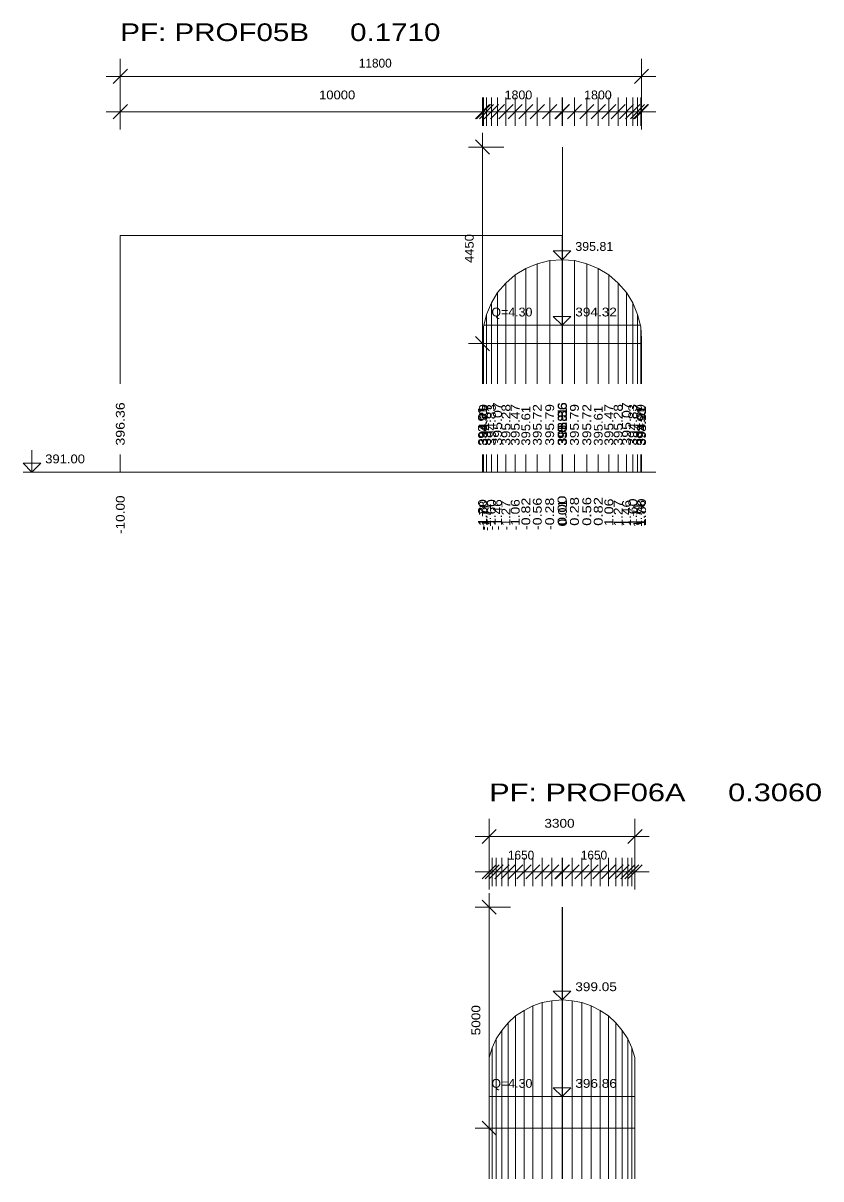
# Model space of a CAD drawing. Extents: x 7 to 442, y -393 to 441.
# Drawn here: x 409.84 to 427.9, y 82.97 to 109.13 of the extents above; entities that cross this region are included whole.
import ezdxf

# ---------------------------------------------------------------- set-up
doc = ezdxf.new("R2010")
doc.units = 0
doc.header["$LTSCALE"] = 0.08
doc.layers.add('7', color=7, linetype='Continuous', lineweight=13)

msp = doc.modelspace()

# ---------------------------------------------------------------- linework, layer by layer
at = {"layer": '7'}
for p, q in [((411.878, 107.766), (412.198, 108.086)), ((412.038, 106.726), (412.038, 108.326)), ((423.678, 107.766), (423.998, 108.086)), ((423.838, 106.726), (423.838, 108.326)), ((411.718, 107.926), (424.158, 107.926)), ((411.878, 106.966), (412.198, 107.286)), ((412.038, 106.806), (412.038, 107.446)), ((420.078, 106.966), (420.398, 107.286)), ((420.078, 106.966), (420.398, 107.286)), ((420.098, 106.966), (420.418, 107.286)), ((420.168, 106.966), (420.488, 107.286)), ((420.238, 106.806), (420.238, 107.446)), ((420.238, 106.806), (420.238, 107.446)), ((420.258, 106.806), (420.258, 107.446)), ((420.278, 106.966), (420.598, 107.286)), ((420.328, 106.806), (420.328, 107.446)), ((420.418, 106.966), (420.738, 107.286)), ((420.438, 106.806), (420.438, 107.446)), ((420.578, 106.806), (420.578, 107.446)), ((420.608, 106.966), (420.928, 107.286)), ((420.768, 106.806), (420.768, 107.446)), ((420.818, 106.966), (421.138, 107.286)), ((420.978, 106.806), (420.978, 107.446)), ((421.058, 106.966), (421.378, 107.286)), ((421.218, 106.806), (421.218, 107.446)), ((421.318, 106.966), (421.638, 107.286)), ((421.478, 106.806), (421.478, 107.446)), ((421.598, 106.966), (421.918, 107.286)), ((421.758, 106.806), (421.758, 107.446)), ((421.878, 106.966), (422.198, 107.286)), ((421.878, 106.966), (422.198, 107.286)), ((421.878, 106.966), (422.198, 107.286)), ((421.888, 106.966), (422.208, 107.286)), ((421.888, 106.966), (422.208, 107.286)), ((422.038, 106.806), (422.038, 107.446)), ((422.038, 106.806), (422.038, 107.446)), ((422.038, 106.806), (422.038, 107.446)), ((422.048, 106.806), (422.048, 107.446)), ((422.048, 106.806), (422.048, 107.446)), ((422.158, 106.966), (422.478, 107.286)), ((422.318, 106.806), (422.318, 107.446)), ((422.438, 106.966), (422.758, 107.286)), ((422.598, 106.806), (422.598, 107.446)), ((422.698, 106.966), (423.018, 107.286)), ((422.858, 106.806), (422.858, 107.446)), ((422.938, 106.966), (423.258, 107.286)), ((423.098, 106.806), (423.098, 107.446)), ((423.148, 106.966), (423.468, 107.286)), ((423.308, 106.806), (423.308, 107.446)), ((423.338, 106.966), (423.658, 107.286)), ((423.478, 106.966), (423.798, 107.286)), ((423.498, 106.806), (423.498, 107.446)), ((423.588, 106.966), (423.908, 107.286)), ((423.638, 106.806), (423.638, 107.446)), ((423.658, 106.966), (423.978, 107.286)), ((423.678, 106.966), (423.998, 107.286)), ((423.678, 106.966), (423.998, 107.286)), ((423.748, 106.806), (423.748, 107.446)), ((423.818, 106.806), (423.818, 107.446)), ((423.838, 106.806), (423.838, 107.446)), ((423.838, 106.806), (423.838, 107.446)), ((411.718, 107.126), (424.158, 107.126)), ((420.238, 101.716), (420.238, 106.646)), ((419.918, 106.326), (420.718, 106.326)), ((420.398, 106.166), (420.078, 106.486)), ((422.048, 100.966), (422.048, 106.326)), ((412.038, 100.966), (412.038, 104.326)), ((422.038, 100.966), (422.038, 104.326)), ((421.478, 100.966), (421.478, 103.686)), ((421.758, 100.966), (421.758, 103.756)), ((422.038, 100.966), (422.038, 103.776)), ((422.038, 103.776), (422.048, 103.776)), ((422.048, 100.966), (422.048, 103.776)), ((422.318, 100.966), (422.318, 103.756)), ((422.598, 100.966), (422.598, 103.686)), ((420.978, 100.966), (420.978, 103.436)), ((421.218, 100.966), (421.218, 103.576)), ((422.858, 100.966), (422.858, 103.576)), ((423.098, 100.966), (423.098, 103.436)), ((420.768, 100.966), (420.768, 103.246)), ((423.308, 100.966), (423.308, 103.246)), ((420.578, 100.966), (420.578, 103.036)), ((423.498, 100.966), (423.498, 103.036)), ((420.438, 100.966), (420.438, 102.796)), ((423.638, 100.966), (423.638, 102.796)), ((420.328, 100.966), (420.328, 102.536)), ((423.748, 100.966), (423.748, 102.536)), ((420.258, 100.966), (420.258, 102.256)), ((420.267, 102.291), (423.809, 102.291)), ((423.818, 100.966), (423.818, 102.256)), ((419.918, 101.876), (420.718, 101.876)), ((420.398, 101.716), (420.078, 102.036)), ((420.238, 100.966), (420.238, 101.976)), ((420.238, 100.966), (420.238, 101.876)), ((422.038, 100.966), (422.038, 101.876)), ((423.838, 100.966), (423.838, 101.976)), ((423.838, 100.966), (423.838, 101.876)), ((412.038, 98.966), (412.038, 99.366)), ((420.238, 98.966), (420.238, 99.366)), ((420.238, 98.966), (420.238, 99.366)), ((420.258, 98.966), (420.258, 99.366)), ((420.328, 98.966), (420.328, 99.366)), ((420.438, 98.966), (420.438, 99.366)), ((420.578, 98.966), (420.578, 99.366)), ((420.768, 98.966), (420.768, 99.366)), ((420.978, 98.966), (420.978, 99.366)), ((421.218, 98.966), (421.218, 99.366)), ((421.478, 98.966), (421.478, 99.366)), ((421.758, 98.966), (421.758, 99.366)), ((422.038, 98.966), (422.038, 99.366)), ((422.038, 98.966), (422.038, 99.366)), ((422.038, 98.966), (422.038, 99.366)), ((422.048, 98.966), (422.048, 99.366)), ((422.048, 98.966), (422.048, 99.366)), ((422.318, 98.966), (422.318, 99.366)), ((422.598, 98.966), (422.598, 99.366)), ((422.858, 98.966), (422.858, 99.366)), ((423.098, 98.966), (423.098, 99.366)), ((423.308, 98.966), (423.308, 99.366)), ((423.498, 98.966), (423.498, 99.366)), ((423.638, 98.966), (423.638, 99.366)), ((423.748, 98.966), (423.748, 99.366)), ((423.818, 98.966), (423.818, 99.366)), ((423.838, 98.966), (423.838, 99.366)), ((423.838, 98.966), (423.838, 99.366)), ((409.838, 98.966), (424.158, 98.966)), ((420.388, 89.516), (420.388, 91.116)), ((423.688, 89.516), (423.688, 91.116)), ((420.228, 90.556), (420.548, 90.876)), ((423.528, 90.556), (423.848, 90.876)), ((420.068, 90.716), (424.008, 90.716)), ((420.228, 89.756), (420.548, 90.076)), ((420.228, 89.756), (420.548, 90.076)), ((420.298, 89.756), (420.618, 90.076)), ((420.388, 89.596), (420.388, 90.236)), ((420.388, 89.596), (420.388, 90.236)), ((420.388, 89.756), (420.708, 90.076)), ((420.458, 89.596), (420.458, 90.236)), ((420.518, 89.756), (420.838, 90.076)), ((420.548, 89.596), (420.548, 90.236)), ((420.658, 89.756), (420.978, 90.076)), ((420.678, 89.596), (420.678, 90.236)), ((420.818, 89.596), (420.818, 90.236)), ((420.828, 89.756), (421.148, 90.076)), ((420.988, 89.596), (420.988, 90.236)), ((421.018, 89.756), (421.338, 90.076)), ((421.178, 89.596), (421.178, 90.236)), ((421.218, 89.756), (421.538, 90.076)), ((421.378, 89.596), (421.378, 90.236)), ((421.428, 89.756), (421.748, 90.076)), ((421.588, 89.596), (421.588, 90.236)), ((421.648, 89.756), (421.968, 90.076)), ((421.808, 89.596), (421.808, 90.236)), ((421.878, 89.756), (422.198, 90.076)), ((421.878, 89.756), (422.198, 90.076)), ((421.878, 89.756), (422.198, 90.076)), ((421.888, 89.756), (422.208, 90.076)), ((421.888, 89.756), (422.208, 90.076)), ((422.038, 89.596), (422.038, 90.236)), ((422.038, 89.596), (422.038, 90.236)), ((422.038, 89.596), (422.038, 90.236)), ((422.048, 89.596), (422.048, 90.236)), ((422.048, 89.596), (422.048, 90.236)), ((422.108, 89.756), (422.428, 90.076)), ((422.268, 89.596), (422.268, 90.236)), ((422.328, 89.756), (422.648, 90.076)), ((422.488, 89.596), (422.488, 90.236)), ((422.538, 89.756), (422.858, 90.076)), ((422.698, 89.596), (422.698, 90.236)), ((422.738, 89.756), (423.058, 90.076)), ((422.898, 89.596), (422.898, 90.236)), ((422.928, 89.756), (423.248, 90.076)), ((423.088, 89.596), (423.088, 90.236)), ((423.098, 89.756), (423.418, 90.076)), ((423.238, 89.756), (423.558, 90.076)), ((423.258, 89.596), (423.258, 90.236)), ((423.368, 89.756), (423.688, 90.076)), ((423.398, 89.596), (423.398, 90.236)), ((423.458, 89.756), (423.778, 90.076)), ((423.528, 89.596), (423.528, 90.236)), ((423.528, 89.756), (423.848, 90.076)), ((423.528, 89.756), (423.848, 90.076)), ((423.618, 89.596), (423.618, 90.236)), ((423.688, 89.596), (423.688, 90.236)), ((423.688, 89.596), (423.688, 90.236)), ((420.068, 89.916), (424.008, 89.916)), ((420.548, 88.956), (420.228, 89.276)), ((420.388, 83.956), (420.388, 89.436)), ((420.068, 89.116), (420.868, 89.116)), ((422.038, 82.966), (422.038, 89.116)), ((422.048, 82.966), (422.048, 89.116)), ((421.378, 82.966), (421.378, 86.886)), ((421.588, 82.966), (421.588, 86.956)), ((421.808, 82.966), (421.808, 86.996)), ((422.038, 82.966), (422.038, 87.016)), ((422.038, 87.016), (422.048, 87.016)), ((422.048, 82.966), (422.048, 87.016)), ((422.268, 82.966), (422.268, 86.996)), ((422.488, 82.966), (422.488, 86.956)), ((422.698, 82.966), (422.698, 86.886)), ((420.988, 82.966), (420.988, 86.656)), ((421.178, 82.966), (421.178, 86.776)), ((422.898, 82.966), (422.898, 86.776)), ((423.088, 82.966), (423.088, 86.656)), ((420.818, 82.966), (420.818, 86.496)), ((423.258, 82.966), (423.258, 86.496)), ((420.548, 82.966), (420.548, 86.136)), ((420.678, 82.966), (420.678, 86.326)), ((423.398, 82.966), (423.398, 86.326)), ((423.528, 82.966), (423.528, 86.136)), ((420.458, 82.966), (420.458, 85.936)), ((423.618, 82.966), (423.618, 85.936)), ((420.388, 82.966), (420.388, 85.716)), ((423.688, 82.966), (423.688, 85.716)), ((420.388, 84.828), (423.688, 84.828)), ((420.548, 83.956), (420.228, 84.276)), ((420.068, 84.116), (420.868, 84.116)), ((420.388, 82.966), (420.388, 84.116)), ((422.038, 82.966), (422.038, 84.116)), ((423.688, 82.966), (423.688, 84.116))]:
    msp.add_line(p, q, dxfattribs=at)
for points in [[(412.038, 104.326), (422.038, 104.326), (422.038, 103.776), (421.758, 103.756), (421.478, 103.686), (421.218, 103.576), (420.978, 103.436), (420.768, 103.246), (420.578, 103.036), (420.438, 102.796), (420.328, 102.536), (420.258, 102.256), (420.238, 101.976), (420.238, 101.876), (422.038, 101.876), (423.838, 101.876), (423.838, 101.976), (423.818, 102.256), (423.748, 102.536), (423.638, 102.796), (423.498, 103.036), (423.308, 103.246), (423.098, 103.436), (422.858, 103.576), (422.598, 103.686), (422.318, 103.756), (422.048, 103.776), (422.048, 106.326)], [(422.038, 104.276), (422.038, 103.776), (421.838, 103.976), (422.238, 103.976), (422.038, 103.776)], [(422.038, 102.791), (422.038, 102.291), (421.838, 102.491), (422.238, 102.491), (422.038, 102.291)], [(410.038, 99.466), (410.038, 98.966), (409.838, 99.166), (410.238, 99.166), (410.038, 98.966)], [(422.038, 89.116), (422.038, 87.016), (421.808, 86.996), (421.588, 86.956), (421.378, 86.886), (421.178, 86.776), (420.988, 86.656), (420.818, 86.496), (420.678, 86.326), (420.548, 86.136), (420.458, 85.936), (420.388, 85.716), (420.388, 84.116), (422.038, 84.116), (423.688, 84.116), (423.688, 85.716), (423.618, 85.936), (423.528, 86.136), (423.398, 86.326), (423.258, 86.496), (423.088, 86.656), (422.898, 86.776), (422.698, 86.886), (422.488, 86.956), (422.268, 86.996), (422.048, 87.016), (422.048, 89.116)], [(422.038, 87.516), (422.038, 87.016), (421.838, 87.216), (422.238, 87.216), (422.038, 87.016)], [(422.038, 85.328), (422.038, 84.828), (421.838, 85.028), (422.238, 85.028), (422.038, 84.828)]]:
    msp.add_lwpolyline(points, dxfattribs=at)

# ---------------------------------------------------------------- texts
for s, height, width, p in [('PF: PROF05B     0.1710', 0.4, 1.25, (412.038, 108.726)), ('10000', 0.2, 1.1, (416.538, 107.406)), ('1800', 0.2, 1.05, (420.738, 107.406)), ('1800', 0.2, 1.05, (422.538, 107.406)), ('395.81', 0.2, 1.05, (422.338, 103.976)), ('Q=4.30', 0.2, 1.05, (420.438, 102.491)), ('394.32', 0.2, 1.15, (422.338, 102.491)), ('391.00', 0.2, 1.1, (410.338, 99.166)), ('PF: PROF06A     0.3060', 0.4, 1.3, (420.388, 91.516)), ('3300', 0.2, 1.15, (421.638, 90.916)), ('399.05', 0.2, 1.15, (422.338, 87.216)), ('Q=4.30', 0.2, 1.05, (420.438, 85.028)), ('396.86', 0.2, 1.15, (422.338, 85.028))]:
    msp.add_text(s, height=height, dxfattribs=dict(at, width=width)).set_placement(p)
for s, p in [('11800', (417.438, 108.126)), ('1650', (420.813, 90.196)), ('1650', (422.463, 90.196))]:
    msp.add_text(s, height=0.2, dxfattribs=at).set_placement(p)
for s, width, p in [('4450', 1.1, (420.038, 103.701)), ('396.36 ', 1.2, (412.138, 99.566)), ('394.29 ', 1.15, (420.358, 99.566)), ('394.57 ', 1.15, (420.428, 99.566)), ('394.83 ', 1.15, (420.538, 99.566)), ('395.07 ', 1.2, (420.678, 99.566)), ('395.28 ', 1.15, (420.868, 99.566)), ('395.47 ', 1.15, (421.078, 99.566)), ('395.72 ', 1.15, (421.578, 99.566)), ('395.79 ', 1.15, (421.858, 99.566)), ('396.36 ', 1.2, (422.138, 99.566)), ('398.36 ', 1.2, (422.148, 99.566)), ('395.79 ', 1.15, (422.418, 99.566)), ('395.72 ', 1.15, (422.698, 99.566)), ('395.47 ', 1.15, (423.198, 99.566)), ('395.28 ', 1.15, (423.408, 99.566)), ('395.07 ', 1.2, (423.598, 99.566)), ('394.83 ', 1.15, (423.738, 99.566)), ('394.57 ', 1.15, (423.848, 99.566)), ('394.29 ', 1.15, (423.918, 99.566)), ('394.01 ', 1.1, (420.338, 99.566)), ('393.91 ', 1.05, (420.338, 99.566)), ('395.61 ', 1.1, (421.318, 99.566)), ('395.81 ', 1.05, (422.138, 99.566)), ('393.91 ', 1.05, (422.138, 99.566)), ('395.81 ', 1.05, (422.148, 99.566)), ('395.61 ', 1.1, (422.958, 99.566)), ('394.01 ', 1.1, (423.938, 99.566)), ('393.91 ', 1.05, (423.938, 99.566)), ('-10.00 ', 1.15, (412.138, 97.566)), ('  0.00 ', 1.3, (422.138, 97.566)), ('  0.00 ', 1.3, (422.138, 97.566)), ('  0.00 ', 1.3, (422.138, 97.566)), ('  0.28 ', 1.25, (422.418, 97.566)), ('  0.56 ', 1.25, (422.698, 97.566)), ('  0.82 ', 1.25, (422.958, 97.566)), (' -1.80 ', 1.15, (420.338, 97.566)), (' -1.80 ', 1.15, (420.338, 97.566)), (' -1.78 ', 1.1, (420.358, 97.566)), (' -1.60 ', 1.15, (420.538, 97.566)), (' -1.46 ', 1.15, (420.678, 97.566)), (' -1.27 ', 1.1, (420.868, 97.566)), (' -1.06 ', 1.15, (421.078, 97.566)), (' -0.82 ', 1.2, (421.318, 97.566)), (' -0.56 ', 1.2, (421.578, 97.566)), (' -0.28 ', 1.2, (421.858, 97.566)), ('  0.01 ', 1.15, (422.148, 97.566)), ('  0.01 ', 1.15, (422.148, 97.566)), ('  1.06 ', 1.2, (423.198, 97.566)), ('  1.27 ', 1.15, (423.408, 97.566)), ('  1.46 ', 1.15, (423.598, 97.566)), ('  1.60 ', 1.2, (423.738, 97.566)), ('  1.71 ', 1.05, (423.848, 97.566)), ('  1.78 ', 1.15, (423.918, 97.566)), ('  1.80 ', 1.2, (423.938, 97.566)), ('  1.80 ', 1.2, (423.938, 97.566)), ('5000', 1.15, (420.188, 86.216))]:
    msp.add_text(s, height=0.2, rotation=90, dxfattribs=dict(at, width=width)).set_placement(p)
msp.add_text(' -1.71 ', height=0.2, rotation=90, dxfattribs=at).set_placement((420.428, 97.566))

doc.saveas('drawing.dxf')
